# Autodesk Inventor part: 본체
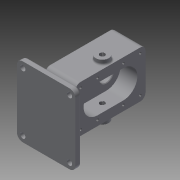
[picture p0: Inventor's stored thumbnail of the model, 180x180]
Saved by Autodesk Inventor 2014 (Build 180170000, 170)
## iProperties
Created: 2020-04
Part Number: 본체
Material: Generic
Document SubType Name: Modeling
Designer: kh
Density: 1 g/cm^3
Appearance: Default
Author: kh
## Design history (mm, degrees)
sketch "스케치1"
  geometry: L1 (-50, -60)-(50, -60); L2 (50, -60)-(50, 60); L3 (50, 60)-(-50, 60); L4 (-50, 60)-(-50, -60); L5 (-50, -60)-(50, 60); L6 (50, -60)-(-50, 60); 1 further point
  constraints: 12 end point, 2 midpoint, 2 parallel, 1 horizontal, 1 perpendicular
  dimensions: "d0" = 100 distance of L3.end L2.end; "d1" = 120 distance of L2.end L1.end
extrude "돌출1" new body sketch "스케치1" distance "d2" = 10; taper "d3" = 0 deg
fillet "모깎기1" dims "d4" = 10
hole "구멍1" diameter "d7" = 9; stored, may be unused: countersink angle "d11" = 90 deg, drill point angle "d13" = 118 deg; dims "d5" = 10, "d6" = 10, "d8" = 6, "d9" = 4, "d10" = 2, "d12" = 8
node "작업 평면1"
sketch "스케치2"
  geometry: L1 (-40, -60)-(40, -60) reference; L2 (50, -50)-(50, 50) reference; L3 (40, 60)-(-40, 60) reference; L4 (-50, 50)-(-50, -50) reference; L5 (-33, 40)-(20, 40); L6 (20, 40)-(20, -40); L7 (20, -40)-(-33, -40); L8 (-33, -40)-(-33, 40); C1 r 4.5 at (-40, -50) reference; C2 r 4.5 at (40, -50) reference; C3 r 4.5 at (-40, 50) reference; C4 r 4.5 at (40, 50) reference; A1 r 10 centre (-40, -50) between (-50, -50) and (-40, -60) reference; A2 r 10 centre (40, -50) between (40, -60) and (50, -50) reference; A3 r 10 centre (40, 50) between (50, 50) and (40, 60) reference; A4 r 10 centre (-40, 50) between (-40, 60) and (-50, 50) reference; 2 further points
  constraints: 8 end point, 2 parallel, 1 horizontal, 1 horizontal alignment, 1 midpoint, 1 perpendicular
  dimensions: "d15" = 70 distance between parallel lines of L6 L4; "d16" = 17 distance between parallel lines of L8 L4; "d17" = 80 distance of L5.end L6.end
extrude "돌출2" join sketch "스케치2" distance "d18" = 120; taper "d19" = 0 deg
sketch "스케치3"
  geometry: L1 (80, 0)-(0, 0) reference; L2 (0, 0)-(0, -120) reference; L3 (80, -120)-(0, -120) reference; L4 (80, 0)-(80, -120) reference; L5 (40, -38)-(40, -82); L6 (16, -38)-(16, -82); L7 (64, -82)-(64, -38); A1 r 24 centre (40, -38) between (64, -38) and (16, -38); A2 r 24 centre (40, -82) between (16, -82) and (64, -82); 3 further points
  constraints: 8 end point, 4 point on circle, 4 tangent, 2 centre point, 2 midpoint, 2 parallel, 1 vertical alignment
  dimensions: "d20" = 48 diameter of A2; "d21" = 44 distance of L5.start L5.end; "d22" = 60 distance from line of point (40, -60) L1
extrude "돌출3" cut sketch "스케치3" distance "d23" = 29; taper "d24" = 0 deg
sketch "스케치4"
  geometry: L1 (16, -82)-(16, -38) reference; L2 (64, -38)-(64, -82) reference; C1 r 12.5 at (40, -38); C2 r 12.5 at (40, -82); A1 r 24 centre (40, -82) between (16, -82) and (64, -82) reference; A2 r 24 centre (40, -38) between (64, -38) and (16, -38) reference; 1 further point
  constraints: 2 centre point, 2 coincident
  dimensions: "d25" = 25 diameter of C1; "d26" = 25 diameter of C2
extrude "돌출4" cut sketch "스케치4" distance "d27" = 15; taper "d28" = 0 deg
sketch "스케치5"
  geometry: L1 (20, 150)-(-33, 150) reference; L2 (-33, 150)-(-33, 30) reference; L3 (20, 30)-(-33, 30) reference; L4 (20, 150)-(20, 30) reference; L5 (-24, 124.5)-(-24, 99.5) reference; L6 (-9, 124.5)-(-9, 99.5) reference; L7 (-33, 112)-(-50, 112); L8 (-33, 131)-(-50, 131); L9 (-50, 131)-(-50, 126.404); L10 (-50, 126.404)-(-49.3, 126); L11 (-49.3, 126)-(-42.7, 126); L12 (-42.7, 126)-(-42.7, 112); L13 (-42.7, 112)-(-33, 112); L14 (-33, 131)-(-33, 112); 2 further points
  constraints: 16 end point, 4 perpendicular, 3 point on line, 2 parallel, 1 collinear, 1 horizontal alignment, 1 midpoint
  dimensions: "d29" = 17 distance of L7.start L7.end; "d30" = 30 deg angle of L11 L10; "d31" = 38 diameter of L8 L7; "d32" = 28 diameter of L11 L7; "d33" = 7.3 horizontal distance of L9.end L11.end; "d34" = 0.7 horizontal distance of L9.end L10.end; "d35" = 17 distance of L8.start L8.end
revolve "회전1" sketch "스케치5" stored, may be unused: angle "d36" = 90 deg
sketch "스케치6"
  geometry: C1 r 14 at (0, 0) reference; C2 r 8.5 at (0, 0); 1 further point
  constraints: 1 centre point, 1 coincident
  dimensions: "d37" = 17 diameter of C2
extrude "돌출5" cut sketch "스케치6" stored distance "d38" = 7.3; taper "d39" = 0 deg
sketch "스케치7"
  geometry: L1 (-40, 0)-(-40, 10) reference; L2 (-40, 0)-(40, 0) reference; L3 (40, 10)-(40, 0) reference; L4 (-40, 10)-(40, 10) reference; L5 (20, 150)-(-33, 150) reference; L6 (-33, 150)-(-33, 30) reference; L7 (20, 30)-(-33, 30) reference; L8 (20, 150)-(20, 30) reference; L9 (-40, 10)-(-50, 10) reference; L10 (-50, 10)-(-50, 0) reference; L11 (-50, 0)-(-40, 0) reference; L12 (-40, 0)-(-40, 10) reference; L13 (20, 10)-(-33, 10); L14 (20, 10)-(8.453, 30); L15 (-33, 10)-(-21.453, 30); L16 (8.453, 30)-(-21.453, 30); 1 further point
  constraints: 8 end point, 2 point on line, 1 collinear, 1 horizontal alignment, 1 perpendicular
  dimensions: "d40" = 53 distance of L13.start L13.end; "d41" = 17 distance of L9.end L13.end; "d42" = 60 deg angle of L15 L13; "d43" = 60 deg angle of L13 L14
extrude "돌출6" join sketch "스케치7" stored distance "d44" = 48; taper "d45" = 0 deg
fillet "모깎기2" dims "d46" = 3
fillet "모깎기3" dims "d47" = 3
fillet "모깎기4" dims "d48" = 3
fillet "모깎기5" dims "d49" = 9
fillet "모깎기6" dims "d50" = 3
chamfer "모따기1" distance "d51" = 1; stored, may be unused: second distance "d52" = 2, angle "d53" = 30 deg
sketch "스케치8"
  geometry: L1 (36.787, -20.42)-(36.787, 20.42); L2 (36.787, 20.42)-(43.213, 20.42); L3 (43.213, 20.42)-(43.213, -20.42); L4 (43.213, -20.42)-(36.787, -20.42); L5 (36.787, -20.42)-(43.213, 20.42); L6 (36.787, 20.42)-(43.213, -20.42); L7 (50, -50)-(50, 50) reference; L8 (-40, -60)-(40, -60) reference; 2 further points
  constraints: 4 end point, 1 midpoint, 2 other
  dimensions: "d54" = 10 distance from line of L7 point (40, 0); "d55" = 60 distance from line of L8 point (40, 0)
feature "엠보싱1" sketch "스케치8" dims "d0" = 100, "d1" = 120, "d56" = 0.5, "d57" = 0
sketch "스케치10"
  geometry: L1 (0, 0)-(62, 0) reference; L2 (52, -120)-(10, -120) reference; L3 (71, -9)-(71, -111) reference; L4 (-9, -111)-(-9, -9) reference; A1 r 9 centre (0, -9) between (0, 0) and (-9, -9) reference; A2 r 9 centre (62, -9) between (71, -9) and (62, 0) reference; A3 r 9 centre (62, -111) between (62, -120) and (71, -111) reference; A4 r 9 centre (0, -111) between (-9, -111) and (0, -120) reference; 9 further points
  constraints: 4 coincident, 4 vertical alignment, 2 horizontal alignment
  dimensions: "d72" = 29 distance of point (62, -38) point (62, -9); "d73" = 44 distance of point (62, -38) point (62, -82)
hole "구멍3" sketch "스케치10" at (0, -9), (62, -9), (62, -111), (0, -111), (0, -38), (62, -38), (0, -82), (62, -82) diameter "d74" = 4.134; stored, may be unused: countersink angle "d78" = 90 deg, drill point angle "d80" = 118 deg; dims "d75" = 10, "d76" = 4, "d77" = 2, "d79" = 12
node "작업 평면2"
sketch "스케치11"
  geometry: L1 (-9, -111)-(-9, -9) reference; L2 (71, -9)-(71, -111) reference; L3 (81, -150)-(-19, -150) reference; L4 (0, 0)-(62, 0) reference; L5 (-17, -60)-(79, -60); L6 (-9, -49)-(-17, -49); L7 (-17, -49)-(-17, -60); L8 (-9, -60)-(-9, -49); L9 (-17, -60)-(-9, -60); 1 further point
  constraints: 10 end point, 2 collinear, 2 point on line, 1 midpoint, 1 parallel, 1 perpendicular
  dimensions: "d83" = 90 distance between parallel lines of L3 L5; "d84" = 8 distance from line of L5.end L2; "d85" = 8 distance from line of L1 L5.start; "d86" = 8 distance of L6.start L6.end; "d87" = 22 diameter of L6 L5
revolve "회전3" sketch "스케치11" stored, may be unused: angle "d88" = 90 deg
hole "구멍4" diameter "d91" = 8.376; stored, may be unused: countersink angle "d95" = 90 deg, drill point angle "d97" = 118 deg; dims "d89" = 10, "d90" = 10, "d92" = 96, "d93" = 4, "d94" = 2, "d96" = 8
fillet "모깎기8" dims "d98" = 3
fillet "모깎기9" dims "d99" = 0.5
node "솔리드1"
mirror "대칭1"
mirror "대칭2"
mirror "대칭4"
node "투영된 루프1"
node "투영된 루프2"
node "투영된 루프3"
node "투영된 루프4"
node "투영된 루프5"
node "투영된 루프6"
node "투영된 루프7"
node "투영된 루프8"
node "투영된 루프9"
other parameters: "d82" = -14
